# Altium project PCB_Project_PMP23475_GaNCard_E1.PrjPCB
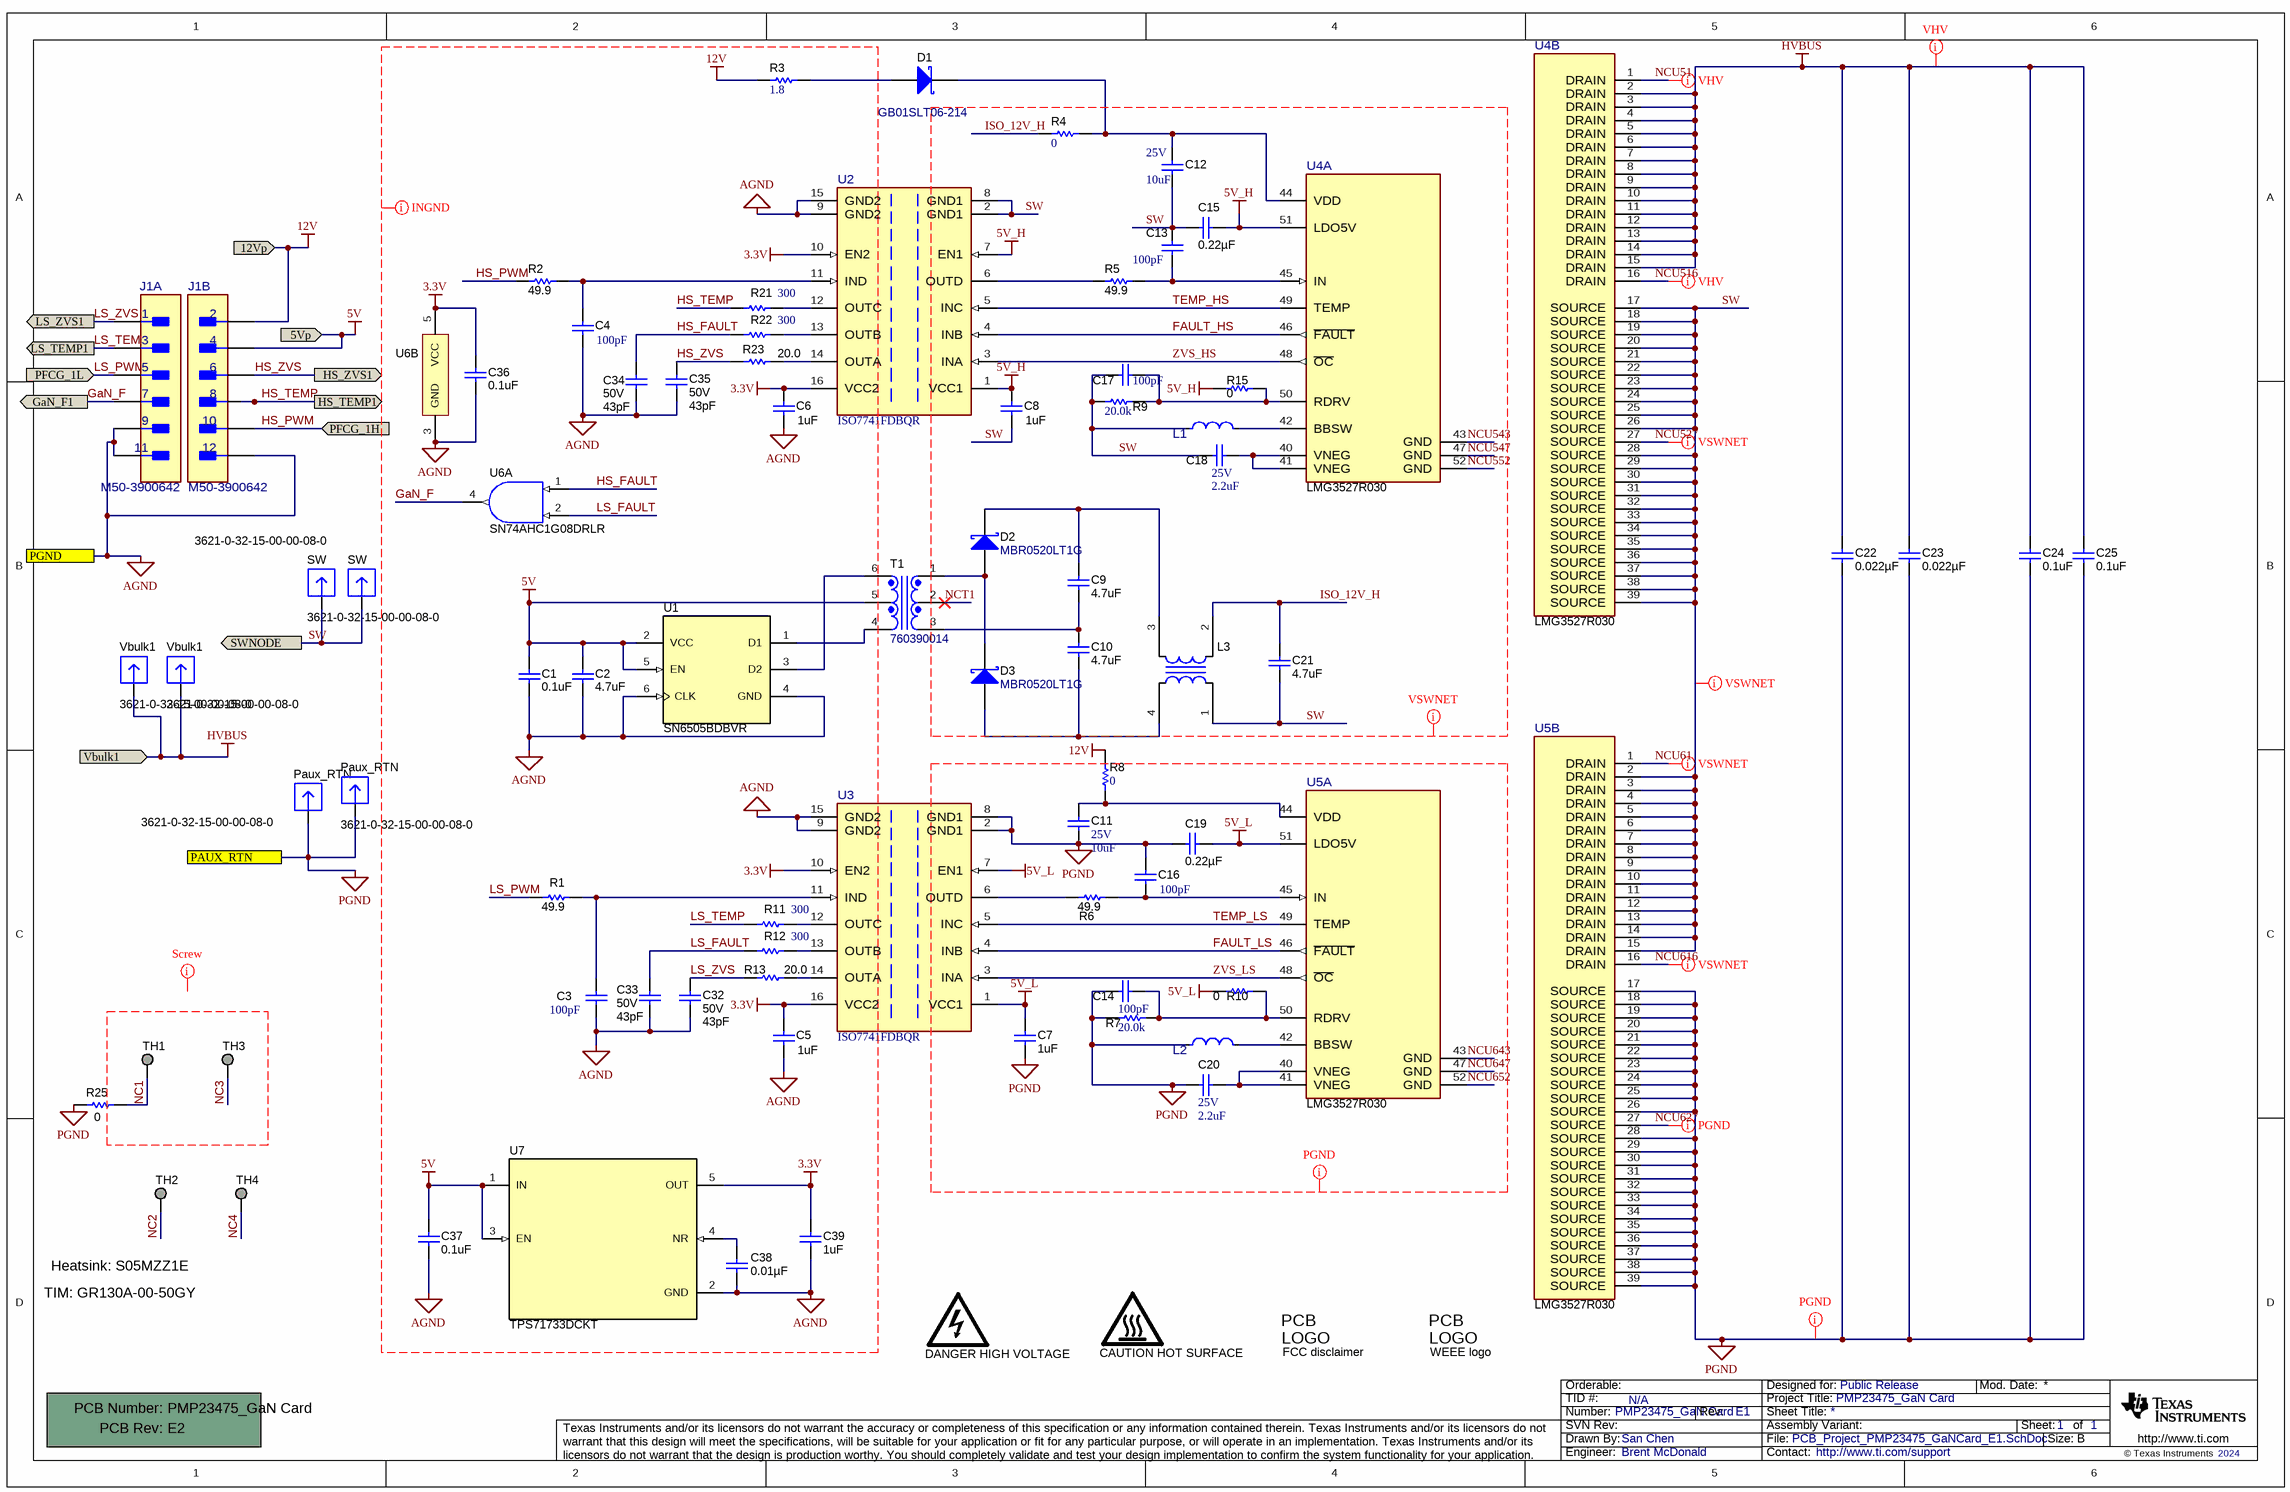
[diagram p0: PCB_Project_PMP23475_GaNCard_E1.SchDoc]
TID: N/A; TechSupport: http://www.ti.com/support; SCH_Rev: E1; PRJ_Title: PMP23475_GaN Card; PRJ_Number: PMP23475_GaN Card; PRJ_Engineer: Brent McDonald; PRJ_Customer: Public Release; PCB_Rev: E2; PCB_Layout: Brent McDonald; CopyrightYear: 2024
1 sheet, 82 parts. Net scope: flat (ports and power ports of the same name join across sheets).
Board file: PCB_Project_PMP23475_GaNCard_E1.PcbDoc

## Sheet PCB_Project_PMP23475_GaNCard_E1.SchDoc
size 431 x 279 mm; DrawnBy: San Chen; SheetNumber: 1; SheetTotal: 1; PageSetup: Record=PageOptions¦CenterHorizontal=True¦CenterVertical=True¦PrintScale=1.00¦XCorrection=1.00¦YCorrection=1.00¦PrintKind=0¦BorderSize=5000000¦LeftOffset=0¦BottomOffset=0¦Orientation=2¦PaperLength=1000¦PaperWidth=1000¦Scale=100¦PaperSource=15¦PrintQuality=600¦MediaType=1¦DitherType=10¦PaperKind=Letter¦PrintScaleMode=1

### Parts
(Parts that share a designator on the sheet are numbered #1, #2 ... from top to bottom, then left to right.)
!PCB1  Printed Circuit Board  (value not drawn)  (mechanical)
C1  ValueDisplayed: 0.1uF  [0402]  (hidden comment: C1005X7R1H104K050BB)
C2  ValueDisplayed: 4.7uF  [0805_HV]  (hidden comment: GCM21BR71C475KA73L)
C3  ValueDisplayed: 100pF  [0402]  (hidden comment: 04025A101FAT2A)
C4  ValueDisplayed: 100pF  [0402]  (hidden comment: 04025A101FAT2A)
C5  ValueDisplayed: 1uF  [0402]  (hidden comment: C1005X5R1E105K050BC)
C6  ValueDisplayed: 1uF  [0402]  (hidden comment: C1005X5R1E105K050BC)
C7  ValueDisplayed: 1uF  [0402]  (hidden comment: C1005X5R1E105K050BC)
C8  ValueDisplayed: 1uF  [0402]  (hidden comment: C1005X5R1E105K050BC)
C9  ValueDisplayed: 4.7uF  [0603]  (hidden comment: C1608X5R1V475K080AC)
C10  ValueDisplayed: 4.7uF  [0603]  (hidden comment: C1608X5R1V475K080AC)
C11  VDC_V: 25V  ValueDisplayed: 10uF  [1206_190]  (hidden comment: C3216X7R1E106M160AE)
C12  VDC_V: 25V  ValueDisplayed: 10uF  [1206_190]  (hidden comment: C3216X7R1E106M160AE)
C13  ValueDisplayed: 100pF  [0402]  (hidden comment: 04025A101FAT2A)
C14  ValueDisplayed: 100pF  [0402]  (hidden comment: 04025A101FAT2A)
C15  ValueDisplayed: 0.22µF  [0402]  (hidden comment: CL05B224KO5NNNC)
C16  ValueDisplayed: 100pF  [0402]  (hidden comment: 04025A101FAT2A)
C17  ValueDisplayed: 100pF  [0402]  (hidden comment: 04025A101FAT2A)
C18  VDC_V: 25V  ValueDisplayed: 2.2uF  [0402]  (hidden comment: GRT155R61E225KE13D)
C19  ValueDisplayed: 0.22µF  [0402]  (hidden comment: CL05B224KO5NNNC)
C20  VDC_V: 25V  ValueDisplayed: 2.2uF  [0402]  (hidden comment: GRT155R61E225KE13D)
C21  ValueDisplayed: 4.7uF  [0603]  (hidden comment: C1608X5R1V475K080AC)
C22  ValueDisplayed: 0.022µF  [1206_190]  (hidden comment: C1206C223KDRACTU)
C23  ValueDisplayed: 0.022µF  [1206_190]  (hidden comment: C1206C223KDRACTU)
C24  ValueDisplayed: 0.1uF  [1812_254]  (hidden comment: C1812W104KDRACTU)
C25  ValueDisplayed: 0.1uF  [1812_254]  (hidden comment: C1812W104KDRACTU)
C32  VDC_V: 50V  ValueDisplayed: 43pF  [0402]  (hidden comment: GCQ1555C1H430JB01D)
C33  VDC_V: 50V  ValueDisplayed: 43pF  [0402]  (hidden comment: GCQ1555C1H430JB01D)
C34  VDC_V: 50V  ValueDisplayed: 43pF  [0402]  (hidden comment: GCQ1555C1H430JB01D)
C35  VDC_V: 50V  ValueDisplayed: 43pF  [0402]  (hidden comment: GCQ1555C1H430JB01D)
C36  ValueDisplayed: 0.1uF  [0402]  (hidden comment: C1005X7R1H104K050BB)
C37  ValueDisplayed: 0.1uF  [0402]  (hidden comment: C1005X7R1H104K050BB)
C38  ValueDisplayed: 0.01µF  [0402]  (hidden comment: C0402C103K4RACTU)
C39  ValueDisplayed: 1uF  [0402]  (hidden comment: C1005X5R1E105K050BC)
D1  GB01SLT06-214  [SMB]
D2  MBR0520LT1G  [SOD-123]
D3  MBR0520LT1G  [SOD-123]
J1  M50-3900642  [FP-M50-3900642_HDR12-MFG]  (parts A,B of 2)
L1  SDEM20161T-4R7MS  [FP-SDEM20161T-4R7MS_SMD2-MFG]  (value not drawn)
L2  SDEM20161T-4R7MS  [FP-SDEM20161T-4R7MS_SMD2-MFG]  (value not drawn)
L3  ACM2520-601-2P-T002  [TDK_ACM2520-2P]  (value not drawn)
LOGO1  DANGER HIGH VOLTAGE  [IEC_HighVoltage_Small]  (no BOM)
LOGO2  CAUTION HOT SURFACE  [IEC_HotSurface_Small]  (no BOM)
Logo3  FCC disclaimer  [FCC_disclaimer]  (no BOM)
Logo4  WEEE logo  [WEEE_Minimum]  (no BOM)
Paux_RTN#1  3621-0-32-15-00-00-08-0  [Mill-Max_3621-0-32-xx-00-00-08-0]
Paux_RTN#2  3621-0-32-15-00-00-08-0  [Mill-Max_3621-0-32-xx-00-00-08-0]
R1  ValueDisplayed: 49.9  [0402]  (hidden comment: RC0402FR-0749R9L)
R2  ValueDisplayed: 49.9  [0402]  (hidden comment: RC0402FR-0749R9L)
R3  ValueDisplayed: 1.8  [1206]  (hidden comment: CRCW12061R80JNEA)  (no BOM)
R4  ValueDisplayed: 0  [0402]  (hidden comment: ERJ-2GE0R00X)
R5  ValueDisplayed: 49.9  [0402]  (hidden comment: RC0402FR-0749R9L)
R6  ValueDisplayed: 49.9  [0402]  (hidden comment: RC0402FR-0749R9L)
R7  ValueDisplayed: 20.0k  [0402]  (hidden comment: CRCW040220K0FKED)
R8  ValueDisplayed: 0  [1206]  (hidden comment: ERJ-8GEY0R00V)
R9  ValueDisplayed: 20.0k  [0402]  (hidden comment: CRCW040220K0FKED)
R10  ValueDisplayed: 0  [0402]  (hidden comment: ERJ-2GE0R00X)
R11  ValueDisplayed: 300  [0402]  (hidden comment: CRCW0402300RJNED)
R12  ValueDisplayed: 300  [0402]  (hidden comment: CRCW0402300RJNED)
R13  ValueDisplayed: 20.0  [0402]  (hidden comment: CRCW040220R0FKED)
R15  ValueDisplayed: 0  [0402]  (hidden comment: ERJ-2GE0R00X)
R21  ValueDisplayed: 300  [0402]  (hidden comment: CRCW0402300RJNED)
R22  ValueDisplayed: 300  [0402]  (hidden comment: CRCW0402300RJNED)
R23  ValueDisplayed: 20.0  [0402]  (hidden comment: CRCW040220R0FKED)
R25  ValueDisplayed: 0  [0805_HV]  (hidden comment: RC0805JR-070RL)
SW#1  3621-0-32-15-00-00-08-0  [Mill-Max_3621-0-32-xx-00-00-08-0]
SW#2  3621-0-32-15-00-00-08-0  [Mill-Max_3621-0-32-xx-00-00-08-0]
T1  760390014  [Wurth_760390013]
TH1  (no value)  [TP_H045P075]  (no BOM)
TH2  (no value)  [TP_H045P075]  (no BOM)
TH3  (no value)  [TP_H045P075]  (no BOM)
TH4  (no value)  [TP_H045P075]  (no BOM)
U1  SN6505BDBVR  [DBV0006A_N]
U2  ISO7741FDBQR  [DBQ0016A-MFG]
U3  ISO7741FDBQR  [DBQ0016A-MFG]
U4  LMG3527R030  [RQS0052A-MFG]  (parts A,B of 2)
U5  LMG3527R030  [RQS0052A-MFG]  (parts A,B of 2)
U6#1  SN74AHC1G08DRLR  [DRL0005A]  (value not drawn)  (part B of 2)
U6#2  SN74AHC1G08DRLR  [DRL0005A]  (part A of 2)
U7  TPS71733DCKT  [DCK0005A_N]
Vbulk1#1  3621-0-32-15-00-00-08-0  [Mill-Max_3621-0-32-xx-00-00-08-0]
Vbulk1#2  3621-0-32-15-00-00-08-0  [Mill-Max_3621-0-32-xx-00-00-08-0]

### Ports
5Vp (in), 12Vp (in), GaN_F1 (out), HS_TEMP1 (out), HS_ZVS1 (out), LS_TEMP1 (out), LS_ZVS1 (out), PAUX_RTN, PFCG_1H (in), PFCG_1L (in), PGND, SWNODE (out), Vbulk1 (in)

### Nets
3.3V: C5.1 C6.1 C36.1 C39.2 U2.10(EN2) U2.16(VCC2) U3.10(EN2) U3.16(VCC2) U6#1.5(VCC) U7.5(OUT)
5V: C1.1 C2.1 C37.1 J1.4 T1.5 U1.2(VCC) U1.5(EN) U7.1(IN) U7.3(EN) ; port 5Vp
5V_H: C8.1 C15.2 R15.1 U2.1(VCC1) U2.7(EN1) U4.51(LDO5V)
5V_L: C7.2 C19.2 R10.1 U3.1(VCC1) U3.7(EN1) U5.51(LDO5V)
12V: J1.2 R3.1 R8.1 ; port 12Vp
AGND: C1.2 C2.2 C3.2 C4.2 C5.2 C6.2 C32.2 C33.2 C34.2 C35.2 C36.2 C37.2 C38.2 C39.1 J1.9 J1.11 J1.12 U1.4(GND) U1.6(CLK) U2.9(GND2) U2.15(GND2) U3.9(GND2) U3.15(GND2) U6#1.3(GND) U7.2(GND) ; port PGND
HVBUS: C22.1 C23.1 C24.1 C25.1 U4.2(DRAIN) U4.3(DRAIN) U4.4(DRAIN) U4.5(DRAIN) U4.6(DRAIN) U4.7(DRAIN) U4.8(DRAIN) U4.9(DRAIN) U4.10(DRAIN) U4.11(DRAIN) U4.12(DRAIN) U4.13(DRAIN) U4.14(DRAIN) U4.15(DRAIN) Vbulk1#1.1 Vbulk1#2.1 ; port Vbulk1
PGND: C7.1 C11.2 C14.1 C16.1 C19.1 C20.2 C22.2 C23.2 C24.2 C25.2 L2.1 Paux_RTN#1.1 Paux_RTN#2.1 R7.1 R25.1 U3.2(GND1) U3.8(GND1) U5.17(SOURCE) U5.18(SOURCE) U5.19(SOURCE) U5.20(SOURCE) U5.21(SOURCE) U5.22(SOURCE) U5.23(SOURCE) U5.24(SOURCE) U5.25(SOURCE) U5.26(SOURCE) U5.28(SOURCE) U5.29(SOURCE) U5.30(SOURCE) U5.31(SOURCE) U5.32(SOURCE) U5.33(SOURCE) U5.34(SOURCE) U5.35(SOURCE) U5.36(SOURCE) U5.37(SOURCE) U5.38(SOURCE) U5.39(SOURCE) ; port PAUX_RTN
FAULT_HS: U2.4(INB) U4.46(~{FAULT})
FAULT_LS: U3.4(INB) U5.46(~{FAULT})
GaN_F: J1.7 U6#2.4(Y) ; port GaN_F1
HS_FAULT: C34.1 R22.2 U6#2.1(A)
HS_PWM: J1.10 R2.1 ; port PFCG_1H
HS_TEMP: J1.8 R21.2 ; port HS_TEMP1
HS_ZVS: C35.1 J1.6 R23.2 ; port HS_ZVS1
ISO_12V_H: C21.1 L3.2 R4.1
LS_FAULT: C33.1 R12.2 U6#2.2(B)
LS_PWM: J1.5 R1.1 ; port PFCG_1L
LS_TEMP: J1.3 R11.2 ; port LS_TEMP1
LS_ZVS: C32.1 J1.1 R13.2 ; port LS_ZVS1
NC1: R25.2 TH1.1
NC2: TH2.1
NC3: TH3.1
NC4: TH4.1
NCT1: T1.2
NCU51: U4.1(DRAIN)
NCU61: U5.1(DRAIN)
NCU516: U4.16(DRAIN)
NCU527: U4.27(SOURCE)
NCU543: U4.43(GND)
NCU547: U4.47(GND)
NCU552: U4.52(GND)
NCU616: U5.16(DRAIN)
NCU627: U5.27(SOURCE)
NCU643: U5.43(GND)
NCU647: U5.47(GND)
NCU652: U5.52(GND)
SW: C8.2 C12.2 C13.1 C15.1 C17.1 C18.2 C21.2 L1.1 L3.1 R9.1 SW#1.1 SW#2.1 U2.2(GND1) U2.8(GND1) U4.17(SOURCE) U4.18(SOURCE) U4.19(SOURCE) U4.20(SOURCE) U4.21(SOURCE) U4.22(SOURCE) U4.23(SOURCE) U4.24(SOURCE) U4.25(SOURCE) U4.26(SOURCE) U4.28(SOURCE) U4.29(SOURCE) U4.30(SOURCE) U4.31(SOURCE) U4.32(SOURCE) U4.33(SOURCE) U4.34(SOURCE) U4.35(SOURCE) U4.36(SOURCE) U4.37(SOURCE) U4.38(SOURCE) U4.39(SOURCE) U5.2(DRAIN) U5.3(DRAIN) U5.4(DRAIN) U5.5(DRAIN) U5.6(DRAIN) U5.7(DRAIN) U5.8(DRAIN) U5.9(DRAIN) U5.10(DRAIN) U5.11(DRAIN) U5.12(DRAIN) U5.13(DRAIN) U5.14(DRAIN) U5.15(DRAIN) ; port SWNODE
TEMP_HS: U2.5(INC) U4.49(TEMP)
TEMP_LS: U3.5(INC) U5.49(TEMP)
ZVS_HS: U2.3(INA) U4.48(~{OC})
ZVS_LS: U3.3(INA) U5.48(~{OC})
NetC3_1: C3.1 R1.2 U3.11(IND)
NetC4_1: C4.1 R2.2 U2.11(IND)
NetC9_1: C9.1 D2.1(K) L3.3
NetC9_2: C9.2 C10.1 T1.3
NetC10_2: C10.2 D3.2(A) L3.4
NetC11_1: C11.1 R8.2 U5.44(VDD)
NetC12_1: C12.1 D1.1(K) R4.2 U4.44(VDD)
NetC13_2: C13.2 R5.1 U4.45(IN)
NetC14_2: C14.2 R7.2 R10.2 U5.50(RDRV)
NetC16_2: C16.2 R6.2 U5.45(IN)
NetC17_2: C17.2 R9.2 R15.2 U4.50(RDRV)
NetC18_1: C18.1 U4.40(VNEG) U4.41(VNEG)
NetC20_1: C20.1 U5.40(VNEG) U5.41(VNEG)
NetC38_1: C38.1 U7.4(NR)
NetD1_2: D1.2(A) R3.2
NetD2_2: D2.2(A) D3.1(K) T1.1
NetL1_2: L1.2 U4.42(BBSW)
NetL2_2: L2.2 U5.42(BBSW)
NetR5_2: R5.2 U2.6(OUTD)
NetR6_1: R6.1 U3.6(OUTD)
NetR11_1: R11.1 U3.12(OUTC)
NetR12_1: R12.1 U3.13(OUTB)
NetR13_1: R13.1 U3.14(OUTA)
NetR21_1: R21.1 U2.12(OUTC)
NetR22_1: R22.1 U2.13(OUTB)
NetR23_1: R23.1 U2.14(OUTA)
NetT1_4: T1.4 U1.1(D1)
NetT1_6: T1.6 U1.3(D2)

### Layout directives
net class INGND: 3.3V, 5V, 12V, AGND, GaN_F, HS_FAULT, HS_PWM, HS_TEMP, HS_ZVS, LS_FAULT, LS_PWM, LS_TEMP, LS_ZVS
net class VSWNET: 5V_H, FAULT_HS, ISO_12V_H, NCT1, NCU61, NCU527, NCU543, NCU547, NCU552, NCU616, SW, TEMP_HS, ZVS_HS
net class PGND: 5V_L, FAULT_LS, NCU627, NCU643, NCU647, NCU652, PGND, TEMP_LS, ZVS_LS
net class Screw: (no net found under the mark)
net class VHV: HVBUS, NCU51, NCU516

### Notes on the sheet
- Heatsink: S05MZZ1E
- TIM: GR130A-00-50GY

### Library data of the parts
!PCB1 = CMP-0003618-2: Manufacturer: Any; PartNumber: PMP23475_GaN Card
C1 C36 C37 = CMP-0006297-2: CAP, CERM, 0.1 uF, 50 V, +/- 10%, X7R, 0402; Manufacturer: TDK; Alternate PartNumber: 885012205037; Alternate Manufacturer: Wurth Elektronik; Polarized: N; CompType: Capacitor; Value: 0.1uF; U/M: EA; Cap_F: 100nF; ESR_ohm: 0.039064; Value1: 0.039064 ohm; VDC_V: 50V; IRMS_A: 8.14669dA; TaMin_C: -55°C; TaMax_C: 125°C; SizeArea_mm2: 0.5; SizeAreaWB_mm2: 3; SizeX_mm: 1; SizeZ_mm: 0.6; AEC Category: Q200
C2 = CMP-0008020-2: CAP, CERM, 4.7 uF, 16 V, +/- 10%, X7R, AEC-Q200 Grade 1, 0805; Manufacturer: MuRata; TaMin_C: -55°C; Polarized: N; SizeAreaWB_mm2: 6.75; Value1: Unknown; U/M: EA; Value: 4.7uF; TaMax_C: 125°C; SizeZ_mm: 1.45; SizeX_mm: 2; SizeY_mm: 1.25; Cap_Case: 0805; Value2: 16V; SizeArea_mm2: 2.5; AEC Qualified: Y; Cap_F: 4.7µF; AEC Grade: 1; AEC Category: Q200
C3 C4 C13 C14 C16 C17 = CMP-0006196-2: CAP, CERM, 100 pF, 50 V, +/- 1%, C0G/NP0, 0402; Manufacturer: AVX; TaMin_C: -55°C; Polarized: N; SizeAreaWB_mm2: 3; Value1: Unknown; U/M: EA; Value: 100pF; TaMax_C: 125°C; SizeZ_mm: 0.6; SizeX_mm: 1; SizeY_mm: 0.5; Value2: 50V; AEC Category: Q200
C5-C8 C39 = CMP-0006276-2: CAP, CERM, 1 uF, 25 V, +/- 10%, X5R, 0402; Manufacturer: TDK; Alternate PartNumber: C1005X5R1E225K050BC; TaMin_C: -55°C; Polarized: N; SizeAreaWB_mm2: 3; Value1: Unknown; U/M: EA; Value: 1uF; TaMax_C: 80°C; SizeZ_mm: 0.6; SizeX_mm: 1; SizeY_mm: 0.5; Value2: 25V; CompType: Capacitor; Cap_F: 1µF; AEC Category: Q200
C9 C10 = CMP-0007022-5: CAP, CERM, 4.7 uF, 35 V, +/- 10%, X5R, 0603; Manufacturer: TDK; TaMin_C: -55°C; ESR_ohm: 3.728m; Polarized: N; SizeAreaWB_mm2: 4.68; Value1: 0.003728 ohm; U/M: EA; Value: 4.7uF; TaMax_C: 85°C; SizeZ_mm: 1; SizeX_mm: 1.6; SizeY_mm: 0.8; Value2: 35V; SizeArea_mm2: 1.28; CompType: Capacitor; Cap_F: 4.7µF; IRMS_A: 2.69359A; AEC Category: Q200
C11 C12 = CMP-0008692-2: CAP, CERM, 10 uF, 25 V, +/- 20%, X7R, 1206_190; Manufacturer: TDK; TaMin_C: -55°C; Polarized: N; SizeAreaWB_mm2: 10.92; Value1: Unknown; U/M: EA; Value: 10uF; TaMax_C: 125°C; SizeZ_mm: 1.9; SizeX_mm: 3.2; SizeY_mm: 1.6; Cap_Case: 1206; SizeArea_mm2: 5.12; Cap_F: 10µF; AEC Category: Q200
C15 C19 = CMP-0860563-1: CAP, CERM, 0.22 µF, 16 V,+/- 10%, X7R, 0402; Manufacturer: Samsung Electro-Mechanics; SizeX_mm: 1; Green_REACh: Incomplete; TaMin_C: -55°C; SizeArea_mm2: 0.5; TaMax_C: 125°C; U/M: EA; Green_Lifecycle: Active; SizeAreaWB_mm2: 3; VDC_V: 16V; AEC Qualified: N; SizeZ_mm: 0.6; AEC Category: Q200; Cap_F: 220nF; Value: 0.22uF
C18 C20 = CMP-0006716-2: CAP, CERM, 2.2 uF, 25 V, +/- 10%, X5R, AEC-Q200 Grade 3, 0402; Manufacturer: MuRata; TaMin_C: -55°C; Polarized: N; SizeAreaWB_mm2: 3; Value1: Unknown; U/M: EA; Value: 2.2uF; TaMax_C: 85°C; SizeZ_mm: 0.6; SizeX_mm: 1; SizeY_mm: 0.5; AEC Qualified: Y; Cap_F: 2.2µF; AEC Category: Q200
C21 = CMP-0007022-5: CAP, CERM, 4.7 uF, 35 V, +/- 10%, X5R, 0603; Manufacturer: TDK; TaMin_C: -55°C; ESR_ohm: 3.728m; Polarized: N; SizeAreaWB_mm2: 4.68; Value1: 0.003728 ohm; U/M: EA; Value: 4.7uF; TaMax_C: 85°C; SizeZ_mm: 1; SizeX_mm: 1.6; SizeY_mm: 0.8; Value2: 35V; SizeArea_mm2: 1.28; Cap_F: 4.7µF; IRMS_A: 2.69359A; AEC Category: Q200
C22 C23 = CMP-0084048-1: CAP, CERM, 0.022 µF, 1000 V,+/- 10%, X7R, AEC-Q200 Grade 1, 1206; Manufacturer: Kemet; Polarized: N; CompType: Capacitor; Value: 0.022uF; U/M: EA; Cap_F: 22nF; VDC_V: 1kV; Value2: 1000V; TaMin_C: -55°C; TaMax_C: 125°C; Cap_Case: 1206; SizeArea_mm2: 5.12; SizeAreaWB_mm2: 10.92; SizeX_mm: 3.2; SizeY_mm: 1.6; SizeZ_mm: 1.9; AEC Category: Q200; AEC Qualified: Y; AEC Grade: 1
C24 C25 = CMP-0009326-2: CAP, CERM, 0.1 uF, 1000 V, +/- 10%, X7R, 1812; Manufacturer: Kemet; Polarized: N; Value: 0.1uF; U/M: EA; Cap_F: 100nF; Value1: Unknown; VDC_V: 1kV; Value2: 1000V; TaMin_C: -55°C; TaMax_C: 125°C; Cap_Case: 1812; AEC Category: Q200; SizeArea_mm2: 14.4; SizeAreaWB_mm2: 23.1; SizeX_mm: 4.5; SizeY_mm: 3.2; SizeZ_mm: 2.54
C32-C35 = CMP-0860835-1: CAP, CERM, 43 pF, 50 V,+/- 5%, C0G/NP0, AEC-Q200 Grade 1, 0402; Manufacturer: MuRata; SizeY_mm: 0.5; SizeZ_mm: 0.6; AEC Qualified: Y; AEC Grade: 1; AEC Category: Q200; U/M: EA; Value: 43pF; Polarized: N; TaMin_C: -55°C; SizeAreaWB_mm2: 3; TaMax_C: 125°C
C38 = CMP-0078218-1: CAP, CERM, 0.01 µF, 16 V,+/- 10%, X7R, 0402; Manufacturer: Kemet; TaMin_C: -55°C; Polarized: N; Green_Lifecycle: Active; SizeAreaWB_mm2: 3; Green_REACh: Passed; U/M: EA; Value: 0.01uF; TaMax_C: 125°C; SizeZ_mm: 0.6; SizeX_mm: 1; SizeY_mm: 0.5; Value2: 16V; CompType: Capacitor; Cap_F: 10nF; AEC Category: Q200
D1 = CMP-0076998-2: Diode, Schottky, 650 V, 1 A, SMB; Manufacturer: GeneSiC Semiconductor; Value1: 1A; SizeZ_mm: 2.6; Value: 650V; SizeAreaWB_mm2: 44.156; TJmax_C: 175°C; RJC_CperW: 3.55; SizeArea_mm2: 21.336; AEC Category: Q101; Value2: 2V; SizeY_mm: 3.81; SizeX_mm: 5.6
D2 D3 = CMP-0028524-2: Diode, Schottky, 20 V, 0.5 A, SOD-123; Manufacturer: ON Semiconductor; Green_REACh: Passed; TJmax_C: 125°C; Value1: 0.5A; SizeZ_mm: 1.35; Value2: 0.385V; Vf_V: 385mV; AEC Category: Q101; SizeY_mm: 1.7; Value: 20V; Io_A: 500mA; SizeX_mm: 3.85; Green_Lifecycle: Active; RJC_CperW: 150; SizeAreaWB_mm2: 13.095; SizeArea_mm2: 6.545
J1 = CMP-0093439-1: Connector Header Through Hole, Right Angle 12 position 0.050" (1.27mm); Manufacturer: Harwin; Conn Gender: Male; Conn Orientation: Horizontal; ContactFinish: Gold,Nickel; Row_Count: 2; SizeZ_mm: 3.55mm; AEC Qualified: No; Current_A: 1A
L1 L2 = CMP-0089347-1: 4.7µH Unshielded Inductor 1.1A 426mOhm Max 0806 (2016 Metric); Manufacturer: Cyntec; AEC Qualified: No; Material: Metal Dust; Isat: 1.26A; Test Frequency: 1MHz; DCR_ohm: 0.426; SizeZ_mm: 1mm; Tolerance_%: 20%
L3 = CMP-0013161-2: Coupled inductor, 0.2 A, 0.45 ohm, SMD; Manufacturer: TDK; SizeAreaWB_mm2: 10.5; DCR_ohm: 0.45; SizeZ_mm: 1.3; SizeX_mm: 2.5; SizeY_mm: 2; SizeArea_mm2: 5
LOGO1 = CMP-0074835-1: IEC 61010-1 High Voltage Warning; Library Reference: IEC_HighVoltage; SymbolCreator: a0412235
LOGO2 = CMP-0074837-1: IEC 61010-1 Hot Surface Warning; Library Reference: IEC_HotSurface; SymbolCreator: a0412235
Logo3 = CMP-0074847-1: FCC_disclaimer; Library Reference: Logo
Logo4 = CMP-0074769-1
Paux_RTN#1 Paux_RTN#2 SW#1 SW#2 Vbulk1#1 Vbulk1#2 = CMP-0082316-1: PCB Pin, 0.04" DIA, Edge-Mount; Manufacturer: Mill-Max; CompType: PCB Pin; ContactFinish: Gold; Gender: Male; Row_Count: 1
R1 R2 R6 = CMP-0026738-1: RES, 49.9, 1%, 0.063 W, 0402; Manufacturer: Yageo America; Value: 49.9; Value_Code: 49R9; Power_W: 63mW; Value2: 0.063W; VDC_V: 50V; TempCo: 100 ppm/C; EIA_Code: E96; U/M: EA; AEC Category: Q200; AEC Qualified: N; SizeArea_mm2: 0.5; SizeX_mm: 1; SizeZ_mm: 0.6
R3 = CMP-0018623-3: RES, 1.8, 5%, 0.25 W, AEC-Q200 Grade 0, 1206; Manufacturer: Vishay-Dale; Power_W: 250mW; TempCo: 200 ppm/C; Value_Code: 1R80; Value: 1.8; EIA_Code: E24; SizeX_mm: 3.2; SizeY_mm: 1.6; SizeZ_mm: 1.35; Value2: 0.25W; SizeArea_mm2: 5.12; AEC Qualified: Y; VDC_V: 200V; AEC Category: Q200; AEC Grade: 0
R4 = CMP-0026992-3: RES, 0, 5%, 0.1 W, AEC-Q200 Grade 0, 0402; Manufacturer: Panasonic; Power_W: 100mW; TempCo: 600 ppm/C; Value_Code: 0000; Value: 0; EIA_Code: E24; SizeX_mm: 1; SizeY_mm: 0.5; SizeZ_mm: 0.6; Value2: 0.1W; AEC Qualified: Y; VDC_V: 50V; AEC Category: Q200; SizeAreaWB_mm2: 3
R5 = CMP-0026738-1: RES, 49.9, 1%, 0.063 W, 0402; Manufacturer: Yageo America; CompType: Resistor; Value: 49.9; Value_Code: 49R9; Power_W: 63mW; Value2: 0.063W; VDC_V: 50V; TempCo: 100 ppm/C; EIA_Code: E96; U/M: EA; AEC Category: Q200; AEC Qualified: N; SizeArea_mm2: 0.5; SizeX_mm: 1; SizeZ_mm: 0.6
R7 R9 = CMP-0026162-1: RES, 20.0 k, 1%, 0.063 W, 0402; Manufacturer: Vishay-Dale; Power_W: 63mW; TempCo: 100 ppm/C; Value_Code: 20k0; U/M: EA; Value: 20.0k; EIA_Code: E96; Res_ohm: 20k; SizeX_mm: 1; SizeY_mm: 0.5; SizeZ_mm: 0.6; Value2: 0.063W; VDC_V: 50V; AEC Category: Q200
R8 = CMP-0018748-3: RES, 0, 5%, 0.25 W, AEC-Q200 Grade 0, 1206; Manufacturer: Panasonic; Power_W: 250mW; TempCo: 600 ppm/C; Value_Code: 0000; Value: 0; EIA_Code: E24; SizeX_mm: 3.2; SizeY_mm: 1.6; SizeZ_mm: 1.35; Value2: 0.25W; SizeArea_mm2: 5.12; AEC Qualified: Y; VDC_V: 200V; AEC Category: Q200; SizeAreaWB_mm2: 10.92
R10 R15 = CMP-0026992-3: RES, 0, 5%, 0.1 W, AEC-Q200 Grade 0, 0402; Manufacturer: Panasonic; Power_W: 100mW; TempCo: 600 ppm/C; Value_Code: 0000; Value: 0; EIA_Code: E24; SizeX_mm: 1; SizeY_mm: 0.5; SizeZ_mm: 0.6; Value2: 0.1W; CompType: Resistor; AEC Qualified: Y; VDC_V: 50V; AEC Category: Q200; SizeAreaWB_mm2: 3
R11 R12 R21 R22 = CMP-0026902-3: RES, 300, 5%, 0.063 W, AEC-Q200 Grade 0, 0402; Manufacturer: Vishay-Dale; Power_W: 63mW; TempCo: 200 ppm/C; Value_Code: 300R; Value: 300; EIA_Code: E24; SizeX_mm: 1; SizeY_mm: 0.5; SizeZ_mm: 0.6; Value2: 0.063W; AEC Qualified: Y; VDC_V: 50V; AEC Category: Q200; AEC Grade: 0
R13 R23 = CMP-0026164-2: RES, 20.0, 1%, 0.063 W, AEC-Q200 Grade 0, 0402; Manufacturer: Vishay-Dale; Power_W: 63mW; TempCo: 100 ppm/C; Value_Code: 20R0; Value: 20.0; EIA_Code: E96; Res_ohm: 20; SizeX_mm: 1; SizeY_mm: 0.5; SizeZ_mm: 0.6; Value2: 0.063W; CompType: Resistor; AEC Qualified: Y; VDC_V: 50V; AEC Category: Q200; AEC Grade: 0
R25 = CMP-0020803-2: RES, 0, 5%, 0.125 W, 0805; Manufacturer: Yageo America; Power_W: 125mW; TempCo: 200 ppm/C; Value_Code: 0000; U/M: EA; Value: 0; EIA_Code: E24; SizeX_mm: 2; SizeY_mm: 1.25; SizeZ_mm: 1.45; Value2: 0.125W; SizeArea_mm2: 2.5; VDC_V: 150V; AEC Category: Q200
T1 = CMP-0030718-1: Transformer, 475uH, SMT; Manufacturer: Wurth Elektronik; DCR_ohm: 0.31; Lp: 475; Ind_H: 475µH
TH1-TH4 = CMP-0003719-1: Testpoint; Manufacturer: Texas Instruments; Key: TP_H0.45P0.75; CompType: Pad
U1 = CMP-0076095-1: Low-Noise 1 A, 420 kHz Transformer Driver, DBV0006A (SOT-23-6); Alternate PartNumber: SN6505BDBVT; Manufacturer: Texas Instruments; SizeArea_mm2: 8.12; SizeAreaWB_mm2: 14.82; SizeX_mm: 2.8; SizeY_mm: 2.9; SizeZ_mm: 1.45; CompType: IC; U/M: EA; Green_Lifecycle: Active; Green_REACh: Passed
U2 U3 = CMP-0089510-1: Manufacturer: Texas Instruments; Nominal Supply Current: 0.8-18mA; SizeZ_mm: 1.75mm; TJmax_C: +150°C; TaMax_C: +125°C; Min Supply Voltage: 2.25V; TaMin_C: -55°C; AEC Qualified: No; Standoff Height: 0.11mm; Max Supply Voltage: 5.5V
U4 U5 = CMP-0089968-1: 650-V 30-mΩ GaN FET with Integrated Driver and Protection; Manufacturer: Texas Instruments; Output Voltage: 520V; Nominal Supply Current: 540uA; Min Supply Voltage: 7.5V; Standoff Height: 0mm; AEC Grade: Grade 1; Max Supply Voltage: 18V; Number Of Outputs: 1; AEC Qualified: Yes; TJmax_C: +125°C; SizeZ_mm: 1mm
U6#1 U6#2 = CMP-0051558-2: Single 2-Input Positive-AND Gate, DRL0005A, LARGE T&R; Manufacturer: Texas Instruments; tpd @ Nom Voltage(Max)(ns): 12.3,7.9; Bits(#): 1; Voltage(Nom)(V): 3.3,5; Output Type: CMOS; VCC(Min)(V): 2; VCC(Max)(V): 5.5; ICC @ Nom Voltage(Max)(mA): 0.01; Rating: Catalog; Gate Type: AND; Technology Family: AHC; Schmitt Trigger: No; Logic: True; F @ Nom Voltage(Max)(Mhz): 75; Output Drive (IOL/IOH)(Max)(mA): 50/-50; AEC Category: Q200; AEC Qualified: N; CompType: IC; SizeArea_mm2: 2.56; SizeX_mm: 1.6; SizeZ_mm: 0.6
U7 = CMP-0035674-3: 150mA, High PSRR, Low Quiescent Current, Low Noise LDO, DCK0005A (SOT-SC70-5); Manufacturer: Texas Instruments; Eco-Plan: Green (RoHS & no Sb/Br); Fixed Output Options(V): 3.3; Vin(Min)(V): 2.5; Iq(Typ)(mA): 0.05; Vdo(Typ)(mV): 170; Accuracy(%): 3; Vin(Max)(V): 6.5; Iout(Max)(A): 0.15; AEC Category: Q200; AEC Qualified: N; CompType: IC; SizeAreaWB_mm2: 9.3; SizeArea_mm2: 4.2; SizeX_mm: 2.1; SizeY_mm: 2.0; SizeZ_mm: 1.1; Rating: Catalog

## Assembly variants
Variant of TIDAXXXX_GaNCard: all parts fitted
001: not fitted C32 C35 D1 R3 R7 R9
